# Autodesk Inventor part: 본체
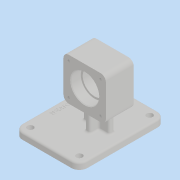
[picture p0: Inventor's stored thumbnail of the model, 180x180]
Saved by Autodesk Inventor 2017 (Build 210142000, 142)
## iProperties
Part Number: 본체
Material: 일반
Document SubType Name: Modeling
Designer: mrc
Density: 1 g/cm^3
Appearance: 기본값
Author: mrc
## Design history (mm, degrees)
sketch "스케치1"
  geometry: L1 (65, 49)-(-65, 49); L2 (-65, 49)-(-65, -49); L3 (-65, -49)-(65, -49); L4 (65, -49)-(65, 49); L5 (65, 49)-(-65, -49); L6 (-65, 49)-(65, -49); 1 further point
  constraints: 12 end point, 2 midpoint, 2 parallel, 1 horizontal, 1 perpendicular
  dimensions: "d0" = 130 distance of L2.end L3.end; "d1" = 98 distance of L1.end L2.end
extrude "돌출1" new body sketch "스케치1" distance "d2" = 10; taper "d3" = 0 deg
sketch "스케치3"
  geometry: L1 (-4, 7)-(4, 7); L2 (4, 7)-(4, -33); L3 (4, -33)-(-4, -33); L4 (-4, -33)-(-4, 7); L5 (-4, 7)-(4, -33); L6 (4, 7)-(-4, -33); L7 (-17, -17)-(17, -17); L8 (17, -17)-(17, -9); L9 (17, -9)-(-17, -9); L10 (-17, -9)-(-17, -17); L11 (-17, -17)-(17, -9); L12 (17, -17)-(-17, -9); L13 (65, -49)-(65, 49) reference; L14 (65, 49)-(-65, 49) reference; 2 further points
  constraints: 24 end point, 5 midpoint, 4 parallel, 2 horizontal, 2 perpendicular
  dimensions: "d9" = 65 distance from line of L13 point (0, -13); "d10" = 62 distance from line of L14 point (0, -13); "d11" = 8 distance between parallel lines of L2 L4; "d12" = 8 distance between parallel lines of L7 L9; "d13" = 34 distance between parallel lines of L8 L10; "d14" = 40 distance between parallel lines of L1 L3
sketch "스케치8"
  geometry: L1 (38, -19)-(102, -19); L2 (102, -19)-(102, 45); L3 (102, 45)-(38, 45); L4 (38, 45)-(38, -19); L5 (38, -19)-(102, 45); L6 (102, -19)-(38, 45); L7 (0, -49)-(10, -49) reference; L8 (0, -49)-(0, 49) reference; 2 further points
  constraints: 12 end point, 2 midpoint, 2 parallel, 1 horizontal, 1 perpendicular
  dimensions: "d33" = 62 distance from line of L7 point (70, 13); "d34" = 70 distance from line of L8 point (70, 13); "d35" = 64 distance of L1.end L2.end; "d36" = 64 distance of L2.end L3.end
extrude "돌출7" join sketch "스케치8" stored distance "d37" = 42; taper "d38" = 0 deg
extrude "돌출8" join sketch "스케치3" stored distance "d39" = 42; taper "d40" = 0 deg
sketch "스케치9"
  geometry: L1 (45, 102)-(-19, 102) reference; L2 (-19, 102)-(-19, 38) reference; C1 r 21 at (13, 70); 3 further points
  constraints: 2 midpoint, 1 centre point, 1 horizontal alignment, 1 vertical alignment
  dimensions: "d41" = 42 diameter of C1
extrude "돌출9" cut sketch "스케치9" distance "d42" = 15; taper "d43" = 0 deg
sketch "스케치10"
  geometry: C1 r 18 at (0, 0); C2 r 21 at (0, 0) reference; 1 further point
  constraints: 1 centre point, 1 concentric
  dimensions: "d44" = 36 diameter of C1
extrude "돌출10" cut sketch "스케치10" distance "d45" = 40.5; taper "d46" = 0 deg
fillet "모깎기1" dims "d47" = 12
fillet "모깎기2" dims "d48" = 8
sketch "스케치11"
  geometry: C1 r 18 at (13, 70) reference; 2 further points
  dimensions: "d49" = 24 horizontal distance of point (-11, 94) C1.centre; "d50" = 24 horizontal distance of C1.centre point (-11, 94)
hole "구멍1" sketch "스케치11" at (-11, 94) diameter "d51" = 3.242; stored, may be unused: countersink angle "d55" = 90 deg, drill point angle "d57" = 118 deg; dims "d52" = 8, "d53" = 4, "d54" = 2, "d56" = 10
fillet "모깎기3" dims "d64" = 3
fillet "모깎기4" dims "d65" = 3
fillet "모깎기5" dims "d66" = 0.3
chamfer "모따기1" distance "d67" = 1; stored, may be unused: second distance "d68" = 2, angle "d69" = 45 deg
sketch "스케치12"
  geometry: L1 (65, -37)-(65, 37) reference; L2 (53, 49)-(-53, 49) reference; 2 further points
  constraints: 1 other
  dimensions: "d70" = 65 distance from line of L1 point (0, 39); "d71" = 10 distance from line of L2 point (0, 39)
feature "엠보싱1" sketch "스케치12" dims "d0" = 130, "d1" = 98, "d9" = 65, "d10" = 62, "d11" = 8, "d12" = 8, "d13" = 34, "d14" = 40, "d72" = 0.5, "d73" = 0
sketch "스케치13"
  geometry: C1 r 4.5 at (-53, 37); C2 r 4.5 at (53, 37); C3 r 4.5 at (-53, -37); C4 r 4.5 at (53, -37); A1 r 12 centre (-53, 37) between (-53, 49) and (-65, 37) reference; A2 r 12 centre (53, 37) between (65, 37) and (53, 49) reference; A3 r 12 centre (53, -37) between (53, -49) and (65, -37) reference; A4 r 12 centre (-53, -37) between (-65, -37) and (-53, -49) reference; 1 further point
  constraints: 4 centre point, 2 coincident, 2 concentric
  dimensions: "d74" = 9 diameter of C1; "d75" = 9 diameter of C2; "d76" = 9 diameter of C3; "d77" = 9 diameter of C4
extrude "돌출11" cut sketch "스케치13" distance "d78" = 40.5; taper "d79" = 0 deg
node "솔리드1"
mirror "미러1"
pattern_linear "직사각형 패턴1" dims "d60" = 48, "d63" = 48
mirror "미러2"
